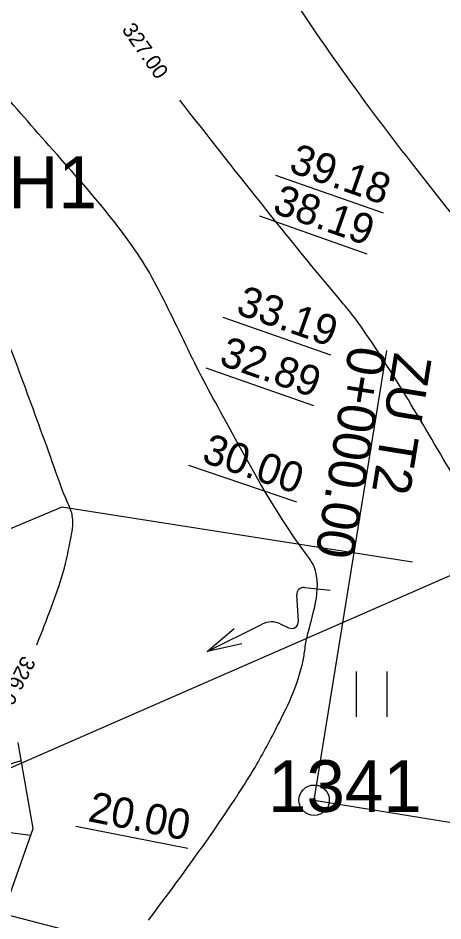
# Model space of a CAD drawing. Extents: x -564037 to -563827, y -1163561 to -1163412.
# Drawn here: x -563949.55 to -563935.58, y -1163485.61 to -1163455.88 of the extents above; entities that cross this region are included whole.
import ezdxf

# ---------------------------------------------------------------- set-up
doc = ezdxf.new("R2010")
doc.units = 0
for name, color, linetype in [('4', 7, 'Continuous'), ('5', 7, 'Continuous'), ('_popis staničení PH2', 7, 'Continuous'), ('_popis staničení T2', 7, 'Continuous'), ('Line', 7, 'Continuous'), ('Parcelní čísla', 7, 'Continuous'), ('podélný profil', 7, 'Continuous'), ('Vrstva 24', 7, 'Continuous'), ('Vrstva 25', 7, 'Continuous'), ('Vrstva 26', 7, 'Continuous'), ('Značky kultur', 7, 'Continuous')]:
    doc.layers.add(name, color=color, linetype=linetype)

msp = doc.modelspace()

# ---------------------------------------------------------------- linework, layer by layer
for points in [[(-563936.58, -1163473.788), (-563948.11, -1163471.977), (-563953.964, -1163474.44)], [(-563949.555, -1163479.73), (-563949.499, -1163480.058), (-563949.499, -1163480.059), (-563949.295, -1163481.246), (-563949.069, -1163482.565), (-563949.069, -1163482.572), (-563950.476, -1163486.561)]]:
    msp.add_lwpolyline(points)
at = {"layer": '5'}
for p, q in [((-563952.243, -1163481.627), (-563927.696, -1163470.887)), ((-563977.993, -1163478.142), (-563940.586, -1163487.812)), ((-563939.818, -1163481.63), (-563906.789, -1163486.973))]:
    msp.add_line(p, q, dxfattribs=at)
at = {"layer": '_popis staničení PH2'}
for p, q in [((-563937.533, -1163462.301), (-563941.071, -1163461.058)), ((-563938.068, -1163463.649), (-563941.606, -1163462.406)), ((-563939.272, -1163466.978), (-563942.81, -1163465.735)), ((-563939.825, -1163468.651), (-563943.363, -1163467.408)), ((-563940.39, -1163471.821), (-563943.94, -1163470.612)), ((-563943.975, -1163483.225), (-563947.654, -1163482.498))]:
    msp.add_line(p, q, dxfattribs=at)
at = {"layer": '_popis staničení T2'}
msp.add_lwpolyline([(-563939.818, -1163481.63), (-563937.423, -1163466.822)], dxfattribs=at)
msp.add_circle((-563939.818, -1163481.63), 0.5, dxfattribs=at)
at = {"layer": 'Line'}
for p, q in [((-563955.699, -1163482.25), (-563949.453, -1163480.323)), ((-563950.319, -1163482.626), (-563949.141, -1163482.778))]:
    msp.add_line(p, q, dxfattribs=at)
at = {"layer": 'podélný profil'}
for points in [[(-563940.139, -1163474.63), (-563939.292, -1163474.714)], [(-563940.335, -1163475.736), (-563940.387, -1163474.868)], [(-563943.329, -1163476.732), (-563941.525, -1163475.83)], [(-563940.935, -1163475.823), (-563940.656, -1163475.954)], [(-563942.194, -1163476.48), (-563943.329, -1163476.732), (-563942.446, -1163475.975)]]:
    msp.add_lwpolyline(points, dxfattribs=at)
for centre, radius, start, end in [((-563940.161, -1163474.854), 0.226, 84.2679, 183.3851), ((-563941.222, -1163476.436), 0.677, 64.8623, 116.5568), ((-563940.561, -1163475.749), 0.226, 244.8644, 3.4114)]:
    msp.add_arc(centre, radius, start, end, dxfattribs=at)
at = {"layer": 'Vrstva 24'}
for points in [[(-563918.729, -1163464.145), (-563920.473, -1163462.326), (-563920.745, -1163462.022), (-563920.932, -1163461.793), (-563924.077, -1163457.593), (-563924.805, -1163456.496), (-563925.51, -1163455.385), (-563926.863, -1163453.13), (-563927.093, -1163452.732), (-563927.34, -1163452.298), (-563929.891, -1163447.793), (-563932.416, -1163443.315), (-563932.865, -1163442.535), (-563938.357, -1163433.346), (-563938.437, -1163433.211), (-563940.917, -1163429.186)], [(-563948.938, -1163476.52), (-563948.45, -1163475.26), (-563947.979, -1163473.791), (-563947.826, -1163473.055), (-563947.76, -1163472.318), (-563947.801, -1163472.127), (-563947.912, -1163471.854), (-563948.426, -1163470.488), (-563948.923, -1163469.115), (-563949.425, -1163467.743), (-563949.955, -1163466.38), (-563952.19, -1163462.283), (-563953.432, -1163460.556), (-563954.94, -1163458.55), (-563956.468, -1163456.56), (-563957.991, -1163454.564), (-563959.48, -1163452.54), (-563962.42, -1163447.812), (-563963.74, -1163445.355), (-563965.037, -1163442.878), (-563965.052, -1163442.844), (-563965.079, -1163442.739), (-563965.877, -1163440.223)], [(-563919.378, -1163476.01), (-563920.124, -1163475.135), (-563923.224, -1163471.065), (-563923.696, -1163470.358), (-563924.164, -1163469.694), (-563926.769, -1163466.405), (-563928.095, -1163464.779), (-563929.404, -1163463.14), (-563932.31, -1163459.338), (-563933.826, -1163457.042), (-563935.107, -1163454.848), (-563938.341, -1163449.378), (-563939.751, -1163446.922), (-563941.145, -1163444.457), (-563942.639, -1163441.761)], [(-563941.26, -1163493.011), (-563939.004, -1163490.701), (-563935.168, -1163486.585), (-563933.596, -1163484.774), (-563933.04, -1163483.789), (-563932.447, -1163481.939), (-563932.386, -1163481.578), (-563932.335, -1163479.091), (-563932.359, -1163478.881), (-563932.37, -1163478.699), (-563932.356, -1163477.982), (-563932.286, -1163477.265), (-563932.226, -1163476.548), (-563932.242, -1163475.831), (-563932.273, -1163475.745), (-563932.328, -1163475.651), (-563935.188, -1163471.035), (-563938.348, -1163465.934), (-563938.454, -1163465.786), (-563938.858, -1163465.285), (-563944.231, -1163458.582)], [(-563939.075, -1163507.623), (-563938.225, -1163507.164), (-563937.324, -1163506.641), (-563936.436, -1163506.097), (-563935.549, -1163505.552), (-563934.649, -1163505.03), (-563930.625, -1163502.906), (-563929.451, -1163502.347), (-563928.196, -1163501.635), (-563924.955, -1163499.225), (-563920.602, -1163495.57), (-563920.316, -1163495.267), (-563915.394, -1163488.268), (-563914.823, -1163487.183), (-563914.579, -1163485.87), (-563914.81, -1163484.102), (-563915.208, -1163482.646), (-563915.847, -1163480.252), (-563916.025, -1163479.9), (-563916.675, -1163479.113), (-563917.077, -1163478.648)]]:
    msp.add_spline(points, degree=3, dxfattribs=at)
at = {"layer": 'Vrstva 26'}
for points in [[(-563933.459, -1163464.585), (-563936.662, -1163460.582), (-563938.758, -1163457.78), (-563942.843, -1163451.434), (-563944.758, -1163447.972), (-563948.452, -1163440.733), (-563948.995, -1163439.651), (-563949.552, -1163438.67), (-563950.173, -1163437.663), (-563950.808, -1163436.665), (-563951.442, -1163435.666), (-563952.055, -1163434.655), (-563954.286, -1163430.739), (-563955.082, -1163429.278)], [(-563945.261, -1163485.579), (-563942.429, -1163481.606), (-563942.364, -1163481.506), (-563941.862, -1163480.718), (-563941.1, -1163479.337), (-563940.179, -1163477.031), (-563940.14, -1163476.815), (-563940.109, -1163476.584), (-563939.736, -1163474.248), (-563939.829, -1163473.919), (-563940.073, -1163473.538), (-563942.893, -1163468.839), (-563943.521, -1163467.678), (-563944.104, -1163466.494), (-563944.685, -1163465.307), (-563945.306, -1163464.14), (-563945.974, -1163463.136), (-563948.418, -1163460.207), (-563952.009, -1163455.848), (-563952.987, -1163454.388), (-563953.586, -1163453.328), (-563954.161, -1163452.255), (-563954.736, -1163451.183), (-563955.25, -1163450.271)], [(-563938.486, -1163500.528), (-563938.463, -1163500.513), (-563937.665, -1163500.022), (-563936.97, -1163499.566), (-563930.777, -1163494.949), (-563928.884, -1163493.45), (-563928.656, -1163493.192), (-563928.195, -1163492.447), (-563924.372, -1163485.735), (-563923.788, -1163484.5), (-563923.604, -1163483.639), (-563923.611, -1163481.604), (-563923.712, -1163481.017), (-563924.518, -1163478.475), (-563924.689, -1163477.919), (-563924.751, -1163477.798), (-563925.518, -1163476.583), (-563926.306, -1163475.384), (-563927.092, -1163474.184), (-563927.851, -1163472.968), (-563928.532, -1163471.813), (-563929.192, -1163470.645), (-563929.849, -1163469.476), (-563930.525, -1163468.317), (-563930.688, -1163468.07), (-563931.156, -1163467.471), (-563931.276, -1163467.321)]]:
    msp.add_spline(points, degree=3, dxfattribs=at)
at = {"layer": 'Značky kultur'}
for p, q in [((-563938.421, -1163478.89), (-563938.421, -1163477.39)), ((-563937.42, -1163478.89), (-563937.42, -1163477.39))]:
    msp.add_line(p, q, dxfattribs=at)

# ---------------------------------------------------------------- texts
at = {"layer": '4'}
msp.add_text('Zemní hrázka PH1', height=1.70472, rotation=360, dxfattribs=at).set_placement((-563965.961, -1163462.139))
at = {"layer": '_popis staničení PH2'}
for s, rotation, p in [('39.18', 340.6443, (-563940.689, -1163460.928)), ('38.19', 340.6443, (-563941.224, -1163462.275)), ('33.19', 340.6443, (-563942.428, -1163465.604)), ('32.89', 340.6443, (-563942.981, -1163467.277)), ('30.00', 341.1778, (-563943.554, -1163470.479)), ('20.00', 348.8173, (-563947.289, -1163482.315))]:
    msp.add_text(s, height=1, rotation=rotation, dxfattribs=at).set_placement(p)
at = {"layer": '_popis staničení T2'}
for s, p in [('0+000.00', (-563938.657, -1163466.623)), ('ZU T2 ', (-563937.176, -1163466.862))]:
    msp.add_text(s, height=1.25, rotation=260.811, dxfattribs=at).set_placement(p)
at = {"layer": 'Parcelní čísla'}
msp.add_text('1341', height=1.7, dxfattribs=at).set_placement((-563941.334, -1163482.014))
at = {"layer": 'Vrstva 25'}
for s, rotation, p in [('327.00', 304.901, (-563946.158, -1163456.257)), ('326.00', 242.423, (-563949.394, -1163476.84))]:
    msp.add_text(s, height=0.5, rotation=rotation, dxfattribs=at).set_placement(p)

doc.saveas('drawing.dxf')
